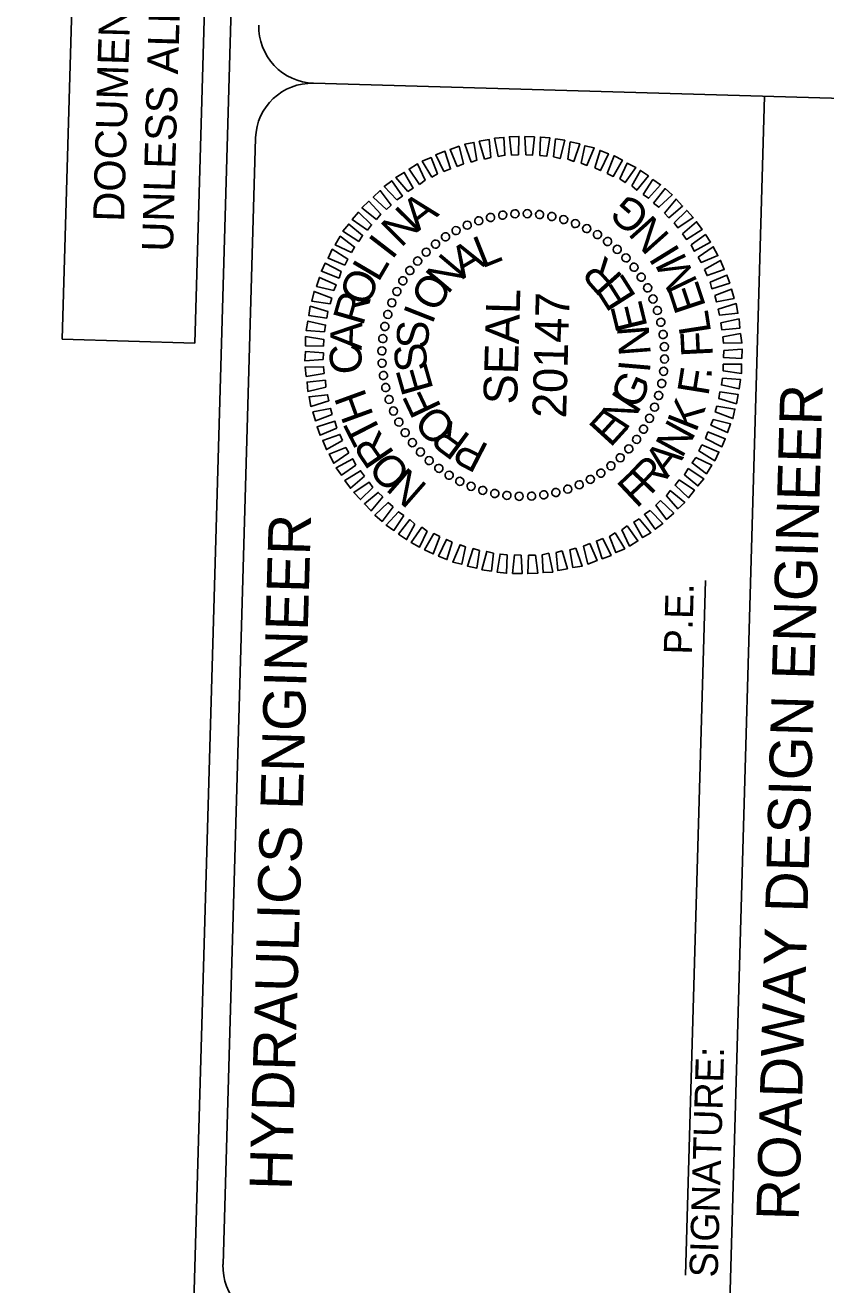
# Model space of a CAD drawing. Extents: x 2097846 to 2099709, y 989477 to 992073.
# Drawn here: x 2099183 to 2099395.9, y 991407.2 to 991742.1 of the extents above; entities that cross this region are included whole.
import ezdxf

# ---------------------------------------------------------------- set-up
doc = ezdxf.new("R2010")
doc.units = 0
for name, color, linetype in [('Sheet PE Seal Cell', 7, 'Continuous'), ('Sheet Sticker Exception Certification CELL', 7, 'Continuous'), ('Sheet Title CELL', 7, 'Continuous')]:
    doc.layers.add(name, color=color, linetype=linetype)

msp = doc.modelspace()

# ---------------------------------------------------------------- linework, layer by layer
at = {"layer": 'Sheet PE Seal Cell'}
for p, q in [((2099303.7, 991690.12), (2099303.7, 991690.12)), ((2099306.8, 991691.01), (2099306.8, 991691.01)), ((2099310.12, 991691.59), (2099310.12, 991691.59)), ((2099313.35, 991691.94), (2099313.35, 991691.94)), ((2099316.66, 991692.07), (2099316.66, 991692.07)), ((2099319.95, 991691.83), (2099319.95, 991691.83)), ((2099323.09, 991691.29), (2099323.09, 991691.29)), ((2099326.37, 991690.44), (2099326.37, 991690.44)), ((2099297.69, 991687.52), (2099297.69, 991687.52)), ((2099300.66, 991688.93), (2099300.66, 991688.93)), ((2099329.41, 991689.38), (2099329.41, 991689.38)), ((2099332.38, 991688.09), (2099332.38, 991688.09)), ((2099335.26, 991686.51), (2099335.26, 991686.51)), ((2099292.19, 991684), (2099292.19, 991684)), ((2099294.87, 991685.8), (2099294.87, 991685.8)), ((2099337.98, 991684.63), (2099337.98, 991684.63)), ((2099289.65, 991681.75), (2099289.65, 991681.75)), ((2099340.54, 991682.53), (2099340.54, 991682.53)), ((2099342.88, 991680.29), (2099342.88, 991680.29)), ((2099285.31, 991676.85), (2099285.31, 991676.85)), ((2099287.41, 991679.49), (2099287.41, 991679.49)), ((2099345.06, 991677.75), (2099345.06, 991677.75)), ((2099283.5, 991674.2), (2099283.5, 991674.2)), ((2099346.86, 991675.07), (2099346.86, 991675.07)), ((2099281.92, 991671.32), (2099281.92, 991671.32)), ((2099348.65, 991672.32), (2099348.65, 991672.32)), ((2099280.56, 991668.35), (2099280.56, 991668.35)), ((2099350.07, 991669.28), (2099350.07, 991669.28)), ((2099279.49, 991665.23), (2099279.49, 991665.23)), ((2099351.25, 991666.24), (2099351.25, 991666.24)), ((2099352.14, 991663.14), (2099352.14, 991663.14)), ((2099278.73, 991662.03), (2099278.73, 991662.03)), ((2099352.72, 991659.9), (2099352.72, 991659.9)), ((2099278.18, 991658.82), (2099278.18, 991658.82)), ((2099353, 991656.59), (2099353, 991656.59)), ((2099277.86, 991655.53), (2099277.86, 991655.53)), ((2099353.13, 991653.28), (2099353.13, 991653.28)), ((2099277.99, 991652.22), (2099277.99, 991652.22)), ((2099352.89, 991650.06), (2099352.89, 991650.06)), ((2099278.35, 991648.98), (2099278.35, 991648.98)), ((2099352.35, 991646.85), (2099352.35, 991646.85)), ((2099278.93, 991645.74), (2099278.93, 991645.74)), ((2099351.58, 991643.65), (2099351.58, 991643.65)), ((2099279.82, 991642.56), (2099279.82, 991642.56)), ((2099281.01, 991639.6), (2099281.01, 991639.6)), ((2099350.51, 991640.53), (2099350.51, 991640.53)), ((2099282.42, 991636.64), (2099282.42, 991636.64)), ((2099349.15, 991637.57), (2099349.15, 991637.57)), ((2099284.14, 991633.81), (2099284.14, 991633.81)), ((2099347.57, 991634.69), (2099347.57, 991634.69)), ((2099285.94, 991631.06), (2099285.94, 991631.06)), ((2099345.69, 991631.96), (2099345.69, 991631.96)), ((2099288.19, 991628.59), (2099288.19, 991628.59)), ((2099290.45, 991626.28), (2099290.45, 991626.28)), ((2099341.35, 991627.06), (2099341.35, 991627.06)), ((2099343.66, 991629.4), (2099343.66, 991629.4)), ((2099293.09, 991624.25), (2099293.09, 991624.25)), ((2099336.2, 991623.08), (2099336.2, 991623.08)), ((2099338.88, 991624.88), (2099338.88, 991624.88)), ((2099295.82, 991622.37), (2099295.82, 991622.37)), ((2099298.7, 991620.79), (2099298.7, 991620.79)), ((2099330.41, 991619.95), (2099330.41, 991619.95)), ((2099333.38, 991621.36), (2099333.38, 991621.36)), ((2099301.66, 991619.43), (2099301.66, 991619.43)), ((2099304.71, 991618.36), (2099304.71, 991618.36)), ((2099307.91, 991617.6), (2099307.91, 991617.6)), ((2099311.12, 991617.05), (2099311.12, 991617.05)), ((2099314.41, 991616.81), (2099314.41, 991616.81)), ((2099317.72, 991616.94), (2099317.72, 991616.94)), ((2099320.96, 991617.29), (2099320.96, 991617.29)), ((2099324.2, 991617.88), (2099324.2, 991617.88)), ((2099327.38, 991618.76), (2099327.38, 991618.76))]:
    msp.add_line(p, q, dxfattribs=at)
for points in [[(2099297.88, 991704.55), (2099295.99, 991709.1), (2099298.41, 991709.93), (2099299.56, 991705.25)], [(2099301.59, 991705.71), (2099299.93, 991710.49), (2099302.35, 991710.94), (2099303.11, 991706.2)], [(2099305.14, 991706.51), (2099303.78, 991711.28), (2099306.42, 991711.73), (2099306.81, 991706.99)], [(2099308.84, 991707.23), (2099307.86, 991712.06), (2099310.34, 991712.29), (2099310.58, 991707.56)], [(2099312.38, 991707.58), (2099311.77, 991712.47), (2099314.32, 991712.55), (2099314.18, 991707.68)], [(2099316.13, 991707.62), (2099315.9, 991712.5), (2099318.45, 991712.43), (2099317.93, 991707.57)], [(2099319.88, 991707.51), (2099320.02, 991712.39), (2099322.56, 991712.16), (2099321.75, 991707.31)], [(2099323.54, 991707.11), (2099324.06, 991711.89), (2099326.52, 991711.52), (2099325.26, 991706.68)], [(2099327.28, 991706.47), (2099327.94, 991711.11), (2099330.47, 991710.58), (2099328.91, 991705.9)], [(2099330.85, 991705.4), (2099331.88, 991710.09), (2099334.34, 991709.5), (2099332.41, 991704.83)], [(2099291.13, 991701.74), (2099288.62, 991705.94), (2099290.98, 991706.92), (2099292.65, 991702.6)], [(2099294.39, 991703.22), (2099292.2, 991707.64), (2099294.63, 991708.62), (2099296.14, 991703.92)], [(2099334.49, 991704.24), (2099335.9, 991708.85), (2099338.12, 991707.96), (2099335.97, 991703.45)], [(2099337.82, 991702.72), (2099339.61, 991707.39), (2099341.83, 991706.21), (2099339.38, 991701.92)], [(2099287.92, 991699.81), (2099285.11, 991703.86), (2099287.33, 991705.3), (2099289.38, 991700.89)], [(2099341.16, 991701.27), (2099343.08, 991705.42), (2099345.37, 991704.3), (2099342.55, 991700.26)], [(2099344.33, 991699.38), (2099346.63, 991703.52), (2099348.76, 991702.03), (2099345.65, 991698.22)], [(2099281.87, 991695.7), (2099278.52, 991699.25), (2099280.52, 991700.77), (2099283.33, 991696.71)], [(2099284.79, 991697.94), (2099281.59, 991701.64), (2099283.81, 991703), (2099286.24, 991698.8)], [(2099347.34, 991697.12), (2099349.93, 991701.09), (2099351.99, 991699.68), (2099348.74, 991696.1)], [(2099279.1, 991693.08), (2099275.59, 991696.41), (2099277.44, 991698.16), (2099280.33, 991694.25)], [(2099350.13, 991694.79), (2099353.16, 991698.68), (2099355.07, 991697.05), (2099351.52, 991693.7)], [(2099276.47, 991690.46), (2099272.58, 991693.57), (2099274.43, 991695.32), (2099277.56, 991691.85)], [(2099352.98, 991692.15), (2099356.08, 991695.89), (2099357.83, 991694.04), (2099354.14, 991690.92)], [(2099274.06, 991687.67), (2099270.02, 991690.42), (2099271.65, 991692.4), (2099275.15, 991689.07)], [(2099355.6, 991689.6), (2099358.92, 991692.88), (2099360.67, 991691.03), (2099356.61, 991688.22)], [(2099357.84, 991686.61), (2099361.54, 991689.88), (2099363.05, 991687.81), (2099358.85, 991685.16)], [(2099271.72, 991684.59), (2099267.53, 991687.34), (2099269.08, 991689.24), (2099272.75, 991686.21)], [(2099360.09, 991683.77), (2099363.92, 991686.44), (2099365.28, 991684.45), (2099360.94, 991682.02)], [(2099269.76, 991681.65), (2099265.47, 991683.72), (2099266.81, 991686.01), (2099270.63, 991683.12)], [(2099361.94, 991680.42), (2099366, 991683.22), (2099367.21, 991680.86), (2099362.8, 991679.04)], [(2099268.02, 991678.32), (2099263.57, 991680.17), (2099264.69, 991682.54), (2099268.81, 991679.95)], [(2099266.49, 991674.91), (2099261.82, 991676.7), (2099262.78, 991678.85), (2099267.07, 991676.62)], [(2099363.65, 991677.14), (2099367.92, 991679.57), (2099368.9, 991677.21), (2099364.35, 991675.54)], [(2099265.12, 991671.58), (2099260.5, 991672.68), (2099261.25, 991675.06), (2099265.69, 991673.13)], [(2099365.13, 991673.8), (2099369.61, 991675.69), (2099370.37, 991673.57), (2099365.6, 991672.06)], [(2099264.12, 991668), (2099259.26, 991668.74), (2099259.86, 991671.35), (2099264.54, 991669.57)], [(2099366.37, 991670.23), (2099370.85, 991671.91), (2099371.53, 991669.48), (2099366.85, 991668.57)], [(2099263.26, 991664.2), (2099258.48, 991664.94), (2099258.85, 991667.4), (2099263.53, 991665.99)], [(2099367.32, 991666.6), (2099372.09, 991668.12), (2099372.54, 991665.55), (2099367.65, 991665.02)], [(2099262.63, 991660.62), (2099257.76, 991660.91), (2099258.21, 991663.45), (2099262.91, 991662.41)], [(2099368.04, 991662.98), (2099372.87, 991664.04), (2099373.03, 991661.56), (2099368.29, 991661.1)], [(2099368.54, 991659.29), (2099373.21, 991660.13), (2099373.59, 991657.65), (2099368.71, 991657.56)], [(2099262.37, 991656.8), (2099257.57, 991656.86), (2099257.57, 991659.34), (2099262.42, 991658.6)], [(2099262.27, 991653.27), (2099257.38, 991652.89), (2099257.53, 991655.36), (2099262.32, 991655)], [(2099368.8, 991655.61), (2099373.69, 991655.99), (2099373.55, 991653.52), (2099368.68, 991653.81)], [(2099262.53, 991649.52), (2099257.79, 991648.75), (2099257.48, 991651.24), (2099262.36, 991651.32)], [(2099368.63, 991652.01), (2099373.5, 991652.02), (2099373.51, 991649.54), (2099368.65, 991650.21)], [(2099262.96, 991645.9), (2099258.2, 991644.76), (2099257.97, 991647.25), (2099262.86, 991647.71)], [(2099368.44, 991648.26), (2099373.23, 991647.9), (2099372.86, 991645.44), (2099368.17, 991646.47)], [(2099263.75, 991642.28), (2099258.98, 991640.76), (2099258.53, 991643.33), (2099263.42, 991643.86)], [(2099367.74, 991644.68), (2099372.6, 991643.94), (2099372.15, 991641.48), (2099367.46, 991642.89)], [(2099264.7, 991638.65), (2099260.22, 991636.98), (2099259.54, 991639.32), (2099264.22, 991640.24)], [(2099366.95, 991640.88), (2099371.73, 991640.07), (2099371.21, 991637.53), (2099366.53, 991639.32)], [(2099265.87, 991635.01), (2099261.46, 991633.11), (2099260.63, 991635.31), (2099265.4, 991636.83)], [(2099365.95, 991637.31), (2099370.57, 991636.12), (2099369.75, 991633.82), (2099365.38, 991635.82)], [(2099267.42, 991631.67), (2099263.15, 991629.31), (2099262.17, 991631.67), (2099266.72, 991633.34)], [(2099364.5, 991633.97), (2099369.18, 991632.19), (2099368.29, 991630.04), (2099363.93, 991632.26)], [(2099269.13, 991628.39), (2099265.07, 991625.66), (2099263.87, 991628.09), (2099268.27, 991629.84)], [(2099362.98, 991630.56), (2099367.5, 991628.63), (2099366.39, 991626.34), (2099362.18, 991628.94)], [(2099270.99, 991625.11), (2099267.16, 991622.45), (2099265.71, 991624.44), (2099270.14, 991626.86)], [(2099361.31, 991627.16), (2099365.6, 991625.16), (2099364.18, 991622.88), (2099360.37, 991625.76)], [(2099273.23, 991622.27), (2099269.53, 991619), (2099268.02, 991621.07), (2099272.22, 991623.65)], [(2099359.27, 991624.29), (2099363.47, 991621.55), (2099361.92, 991619.64), (2099358.32, 991622.6)], [(2099275.47, 991619.21), (2099272.15, 991616), (2099270.4, 991617.85), (2099274.46, 991620.66)], [(2099356.93, 991621.21), (2099360.98, 991618.47), (2099359.42, 991616.49), (2099355.84, 991619.82)], [(2099278.1, 991616.73), (2099274.99, 991612.99), (2099273.24, 991614.84), (2099276.93, 991617.89)], [(2099354.53, 991618.43), (2099358.41, 991615.24), (2099356.56, 991613.57), (2099353.51, 991617.03)], [(2099280.87, 991614.1), (2099277.91, 991610.21), (2099276.01, 991611.84), (2099279.55, 991615.19)], [(2099283.73, 991611.76), (2099281.07, 991607.79), (2099279.01, 991609.2), (2099282.34, 991612.78)], [(2099349.2, 991613.1), (2099352.55, 991609.63), (2099350.55, 991608.11), (2099347.67, 991612.1)], [(2099351.98, 991615.8), (2099355.48, 991612.4), (2099353.56, 991610.73), (2099350.74, 991614.56)], [(2099286.67, 991609.5), (2099284.45, 991605.37), (2099282.31, 991606.85), (2099285.35, 991610.67)], [(2099346.28, 991610.86), (2099349.4, 991607.17), (2099347.19, 991605.88), (2099344.83, 991610)], [(2099289.91, 991607.61), (2099287.92, 991603.39), (2099285.7, 991604.58), (2099288.52, 991608.63)], [(2099293.25, 991606.16), (2099291.47, 991601.56), (2099289.25, 991602.68), (2099291.7, 991606.96)], [(2099339.87, 991607.15), (2099342.45, 991602.94), (2099340.1, 991601.89), (2099338.42, 991606.21)], [(2099343.08, 991609), (2099345.96, 991605.02), (2099343.75, 991603.66), (2099341.69, 991607.92)], [(2099296.58, 991604.64), (2099295.17, 991600.03), (2099292.95, 991600.92), (2099295.1, 991605.43)], [(2099300.15, 991603.41), (2099299.11, 991598.79), (2099296.73, 991599.38), (2099298.66, 991603.98)], [(2099303.8, 991602.48), (2099303.14, 991597.77), (2099300.6, 991598.3), (2099302.16, 991602.98)], [(2099329.48, 991603.09), (2099331.14, 991598.32), (2099328.65, 991597.94), (2099327.89, 991602.61)], [(2099333.19, 991604.34), (2099335.08, 991599.78), (2099332.66, 991598.87), (2099331.52, 991603.63)], [(2099336.6, 991605.66), (2099338.8, 991601.17), (2099336.45, 991600.27), (2099334.93, 991604.96)], [(2099307.53, 991601.77), (2099307.02, 991596.99), (2099304.48, 991597.36), (2099305.74, 991602.2)], [(2099311.19, 991601.29), (2099311.05, 991596.42), (2099308.51, 991596.72), (2099309.32, 991601.5)], [(2099314.94, 991601.26), (2099315.18, 991596.38), (2099312.63, 991596.38), (2099313.14, 991601.31)], [(2099318.69, 991601.23), (2099319.3, 991596.41), (2099316.68, 991596.33), (2099316.89, 991601.2)], [(2099322.23, 991601.73), (2099323.29, 991596.74), (2099320.73, 991596.59), (2099320.5, 991601.33)], [(2099325.85, 991602.37), (2099327.22, 991597.61), (2099324.65, 991597.15), (2099324.26, 991601.89)]]:
    msp.add_lwpolyline(points, close=True, dxfattribs=at)
for centre, major_axis in [((2099300.57, 991688.95), (-0.428, 0.991)), ((2099303.63, 991690.12), (-0.34, 1.02)), ((2099306.78, 991691.01), (-0.25, 1.05)), ((2099310, 991691.63), (-0.16, 1.07)), ((2099313.26, 991691.97), (-0.06, 1.08)), ((2099316.54, 991692.01), (0.03, 1.08)), ((2099319.81, 991691.78), (0.12, 1.07)), ((2099323.05, 991691.26), (0.22, 1.06)), ((2099326.23, 991690.45), (0.31, 1.03)), ((2099329.33, 991689.38), (0.4, 1)), ((2099294.8, 991685.84), (-0.593, 0.901)), ((2099297.61, 991687.52), (-0.512, 0.95)), ((2099332.32, 991688.04), (0.484, 0.964)), ((2099335.18, 991686.44), (0.566, 0.918)), ((2099292.14, 991683.92), (-0.669, 0.846)), ((2099337.89, 991684.6), (0.644, 0.866)), ((2099340.44, 991682.53), (0.717, 0.806)), ((2099287.38, 991679.42), (-0.806, 0.717)), ((2099289.66, 991681.78), (-0.741, 0.785)), ((2099342.79, 991680.25), (0.785, 0.741)), ((2099285.31, 991676.88), (-0.866, 0.644)), ((2099344.93, 991677.77), (0.846, 0.669)), ((2099283.47, 991674.17), (-0.918, 0.566)), ((2099346.85, 991675.11), (0.901, 0.593)), ((2099348.54, 991672.29), (0.95, 0.512)), ((2099281.87, 991671.31), (-0.964, 0.484)), ((2099349.97, 991669.34), (0.991, 0.428)), ((2099279.45, 991665.22), (-1.03, 0.31)), ((2099280.53, 991668.31), (-1, 0.4)), ((2099351.13, 991666.28), (1.02, 0.34)), ((2099278.65, 991662.04), (-1.06, 0.22)), ((2099352.03, 991663.13), (1.05, 0.25)), ((2099278.13, 991658.8), (-1.07, 0.12)), ((2099352.64, 991659.91), (1.07, 0.16)), ((2099277.89, 991655.53), (-1.08, 0.03)), ((2099352.98, 991656.64), (1.08, 0.06)), ((2099277.94, 991652.25), (-1.08, -0.06)), ((2099353.03, 991653.37), (1.08, -0.03)), ((2099278.28, 991648.99), (-1.07, -0.16)), ((2099352.79, 991650.1), (1.07, -0.12)), ((2099278.89, 991645.77), (-1.05, -0.25)), ((2099352.27, 991646.86), (1.06, -0.22)), ((2099279.79, 991642.62), (-1.02, -0.34)), ((2099351.47, 991643.68), (1.03, -0.31)), ((2099280.96, 991639.55), (-0.991, -0.428)), ((2099350.39, 991640.58), (1, -0.4)), ((2099282.39, 991636.6), (-0.95, -0.512)), ((2099349.05, 991637.59), (0.964, -0.484)), ((2099284.07, 991633.79), (-0.901, -0.593)), ((2099345.61, 991632.01), (0.866, -0.644)), ((2099347.45, 991634.73), (0.918, -0.566)), ((2099285.99, 991631.13), (-0.846, -0.669)), ((2099288.13, 991628.65), (-0.785, -0.741)), ((2099343.54, 991629.47), (0.806, -0.717)), ((2099290.48, 991626.37), (-0.717, -0.806)), ((2099338.78, 991624.97), (0.669, -0.846)), ((2099341.26, 991627.12), (0.741, -0.785)), ((2099293.03, 991624.3), (-0.644, -0.866)), ((2099295.74, 991622.46), (-0.566, -0.918)), ((2099336.12, 991623.05), (0.593, -0.901)), ((2099298.6, 991620.86), (-0.484, -0.964)), ((2099301.59, 991619.52), (-0.4, -1)), ((2099304.69, 991618.44), (-0.31, -1.03)), ((2099327.29, 991618.78), (0.34, -1.02)), ((2099330.36, 991619.94), (0.428, -0.991)), ((2099333.31, 991621.37), (0.512, -0.95)), ((2099307.87, 991617.64), (-0.22, -1.06)), ((2099311.11, 991617.12), (-0.12, -1.07)), ((2099314.38, 991616.88), (-0.03, -1.08)), ((2099317.66, 991616.93), (0.06, -1.08)), ((2099320.92, 991617.26), (0.16, -1.07)), ((2099324.14, 991617.88), (0.25, -1.05))]:
    msp.add_ellipse(centre, major_axis=major_axis, ratio=0.999708, dxfattribs=at)
at = {"layer": 'Sheet Sticker Exception Certification CELL'}
for p, q in [((2099192.91, 991658.64), (2099201.55, 991958.57)), ((2099236.79, 991957.56), (2099228.15, 991657.62)), ((2099228.15, 991657.62), (2099192.91, 991658.64))]:
    msp.add_line(p, q, dxfattribs=at)
at = {"layer": 'Sheet Title CELL'}
for p, q in [((2099183.04, 989845.97), (2099244.37, 991975.08)), ((2099499.62, 991719.78), (2099259.72, 991726.7)), ((2099370.11, 991392.37), (2099379.64, 991723.24)), ((2099235.67, 991412.6), (2099244.3, 991712.13)), ((2099358.63, 991409.8), (2099363.95, 991594.53))]:
    msp.add_line(p, q, dxfattribs=at)
for centre, start, end in [((2099260.16, 991741.69), 178.35, 268.35), ((2099259.29, 991711.7), 88.35, 178.35), ((2099250.6, 991412.18), 178.35, 268.35)]:
    msp.add_arc(centre, 15, start, end, dxfattribs=at)

# ---------------------------------------------------------------- texts
at = {"layer": 'Sheet PE Seal Cell'}
for s, height, rotation, p in [('A', 8.45, 37.9667, (2099287.46, 991687.14)), ('N', 8.45, 45.1685, (2099282.98, 991682.77)), ('G', 8.4, 138.9471, (2099349.74, 991692.1)), ('N', 8.4, 131.7695, (2099354.76, 991686.11)), ('I', 8.45, 52.3697, (2099280.56, 991679.53)), ('A', 8.45, 31.1098, (2099299.33, 991674.49)), ('L', 8.45, 21.7504, (2099304.51, 991677.42)), ('I', 8.4, 121.686, (2099357.39, 991681.9)), ('N', 8.45, 49.8262, (2099295.38, 991670.33)), ('R', 8.45, 131.831, (2099342.26, 991675.2)), ('M', 8.4, 115.8396, (2099361.98, 991673.79)), ('O', 8.45, 66.7707, (2099274.05, 991666.97)), ('L', 8.45, 59.5704, (2099276.94, 991673.56)), ('O', 8.45, 59.183, (2099292.39, 991665.39)), ('E', 8.45, 122.4736, (2099345.71, 991669.93)), ('E', 8.4, 108.3412, (2099364.13, 991667.38)), ('R', 8.45, 73.9707, (2099272.85, 991661.97)), ('SEAL', 8.988, 88.3496, (2099313.82, 991641.21)), ('20147', 8.991, 88.3496, (2099326.85, 991637.54)), ('I', 8.45, 68.5392, (2099291.25, 991662.34)), ('E', 8.44, 103.7613, (2099348.56, 991661.97)), ('A', 8.45, 88.3699, (2099272.52, 991655.68)), ('S', 8.45, 87.25, (2099290.16, 991655.92)), ('L', 8.4, 98.7591, (2099365.46, 991660.48)), ('N', 8.45, 94.4059, (2099349.4, 991654.52)), ('F', 8.4, 92.8467, (2099365.92, 991654.13)), ('C', 8.45, 95.5694, (2099272.88, 991649.74)), ('S', 8.45, 96.6052, (2099290.16, 991650.52)), ('E', 8.45, 105.9606, (2099291.66, 991645.37)), ('I', 8.45, 85.0508, (2099349.1, 991649.5)), ('F', 8.4, 80.8685, (2099364.66, 991643.34)), ('.', 8.4, 86.0929, (2099365.47, 991647.95)), ('G', 8.45, 66.3398, (2099346.12, 991639.68)), ('H', 8.45, 109.969, (2099275.77, 991638.33)), ('F', 8.45, 115.3166, (2099293.84, 991640.51)), ('N', 8.45, 56.9835, (2099342.73, 991634)), ('K', 8.4, 68.4319, (2099361.37, 991633.63)), ('O', 8.45, 134.0308, (2099298.13, 991635.51)), ('E', 8.44, 47.6264, (2099338.62, 991629.62)), ('T', 8.45, 117.1693, (2099278.18, 991633.38)), ('R', 8.45, 143.3892, (2099301.8, 991632.85)), ('N', 8.4, 61.3315, (2099357.65, 991626.71)), ('R', 8.45, 124.3701, (2099281.41, 991628.26)), ('P', 8.45, 152.7484, (2099306.68, 991630.39)), ('A', 8.4, 51.7959, (2099353.68, 991621.39)), ('O', 8.45, 131.5713, (2099285.99, 991623.03)), ('R', 8.4, 46.3858, (2099349.29, 991616.97)), ('N', 8.45, 138.7731, (2099290.32, 991619.6)), ('F', 8.4, 43.227, (2099345.57, 991613.47))]:
    msp.add_text(s, height=height, rotation=rotation, dxfattribs=at).set_placement(p)
at = {"layer": 'Sheet Sticker Exception Certification CELL'}
for s, p in [('UNLESS ALL SIGNATURES COMPLETED', (2099222.31, 991681.8)), ('DOCUMENT NOT CONSIDERED FINAL', (2099209.33, 991689.78))]:
    msp.add_text(s, height=8.25, rotation=88.3496, dxfattribs=at).set_placement(p)
at = {"layer": 'Sheet Title CELL'}
for s, height, p in [('ROADWAY DESIGN ENGINEER', 11.25, (2099388.68, 991424.25)), (' HYDRAULICS ENGINEER', 11.25, (2099253.77, 991428.14)), ('P.E.', 7.499, (2099360.3, 991574.72)), ('SIGNATURE:', 7.499, (2099367.14, 991409.14))]:
    msp.add_text(s, height=height, rotation=88.35, dxfattribs=at).set_placement(p)

doc.saveas('drawing.dxf')
